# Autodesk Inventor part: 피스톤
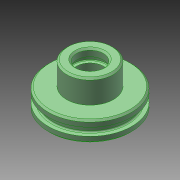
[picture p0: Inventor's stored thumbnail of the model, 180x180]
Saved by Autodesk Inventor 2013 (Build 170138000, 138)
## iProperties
Created: 2023-03
Part Number: 피스톤
Material: 강철, 연강
Document SubType Name: Modeling
Designer: mdu-01
Density: 1 g/cm^3
Author: mdu-01
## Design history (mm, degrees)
sketch "스케치1"
  geometry: L1 (0, 0)-(13, 0); L2 (14, 1)-(14, 6); L3 (14, 6)-(24, 6); L4 (25, 7)-(25, 9.65); L5 (25, 9.65)-(22.8, 9.65); L6 (22, 10.45)-(22, 13.55); L7 (22.8, 14.35)-(25, 14.35); L8 (25, 14.35)-(25, 17); L9 (24, 18)-(14, 18); L10 (14, 18)-(14, 31); L11 (13, 32)-(9, 32); L12 (8, 20)-(0, 20); L13 (0, 20)-(0, 0); L14 (22, 12)-(25, 12); L15 (9, 32)-(8, 31); L16 (14, 31)-(13, 32); L17 (25, 17)-(24, 18); L18 (24, 6)-(25, 7); L19 (13, 0)-(14, 1); L20 (8, 27.6)-(9.6, 27.6); L21 (10, 27.2)-(10, 24.8); L22 (9.6, 24.4)-(8, 24.4); L23 (8, 31)-(8, 27.6); L24 (8, 24.4)-(8, 20); A1 r 0.8 centre (22.8, 10.45) between (22, 10.45) and (22.8, 9.65); A2 r 0.8 centre (22.8, 13.55) between (22.8, 14.35) and (22, 13.55); A3 r 0.4 centre (9.6, 27.2) between (10, 27.2) and (9.6, 27.6); A4 r 0.4 centre (9.6, 24.8) between (9.6, 24.4) and (10, 24.8); 6 further points
  constraints: 48 end point, 11 parallel, 11 point on line, 8 perpendicular, 8 point on circle, 8 tangent, 4 centre point, 3 collinear, 2 equal radius, 2 midpoint, 1 horizontal, 1 other
  dimensions: "d0" = 50 diameter of L4 L13; "d2" = 0.8 radius of A1; "d3" = 32 distance between parallel lines of L11 L1; "d4" = 14 distance between parallel lines of L9 L11; "d5" = 4.7 distance between parallel lines of L5 L7; "d6" = 6 distance between parallel lines of L3 L1; "d7" = 44 diameter of L6 L13; "d8" = 28 diameter of L2 L13; "d10" = 12 distance between parallel lines of L12 L11; "d11" = 1 distance of L11.end point (8, 32); "d12" = 1 distance of L15.end point (8, 32) (= d11); "d13" = 1 distance of L10.end point (14, 32) (= d11); "d14" = 1 distance of L11.start point (14, 32) (= d13); "d15" = 1 distance of L8.end point (25, 18) (= d11); "d16" = 1 distance of L9.start point (25, 18) (= d15); "d17" = 1 distance of L3.end point (25, 6) (= d11); "d18" = 1 distance of L4.start point (25, 6) (= d17); "d19" = 1 distance of L1.end point (14, 0) (= d11); "d20" = 1 distance of L2.start point (14, 0) (= d19); "d31" = 16 diameter of L23 L13; "d32" = 0.4 radius of A3; "d33" = 6 distance from line of point (10, 26) L11; "d34" = 3.2 distance between parallel lines of L22 L20; "d35" = 20 diameter of L21 L13
revolve "회전1" sketch "스케치1" stored, may be unused: angle "d21" = 90 deg
hole "구멍1" diameter "d24" = 9; stored, may be unused: countersink angle "d28" = 90 deg, drill point angle "d30" = 118 deg; dims "d22" = 10, "d23" = 10, "d25" = 6, "d26" = 15, "d27" = 9, "d29" = 8
node "솔리드1"
other parameters: "d9" = 16
